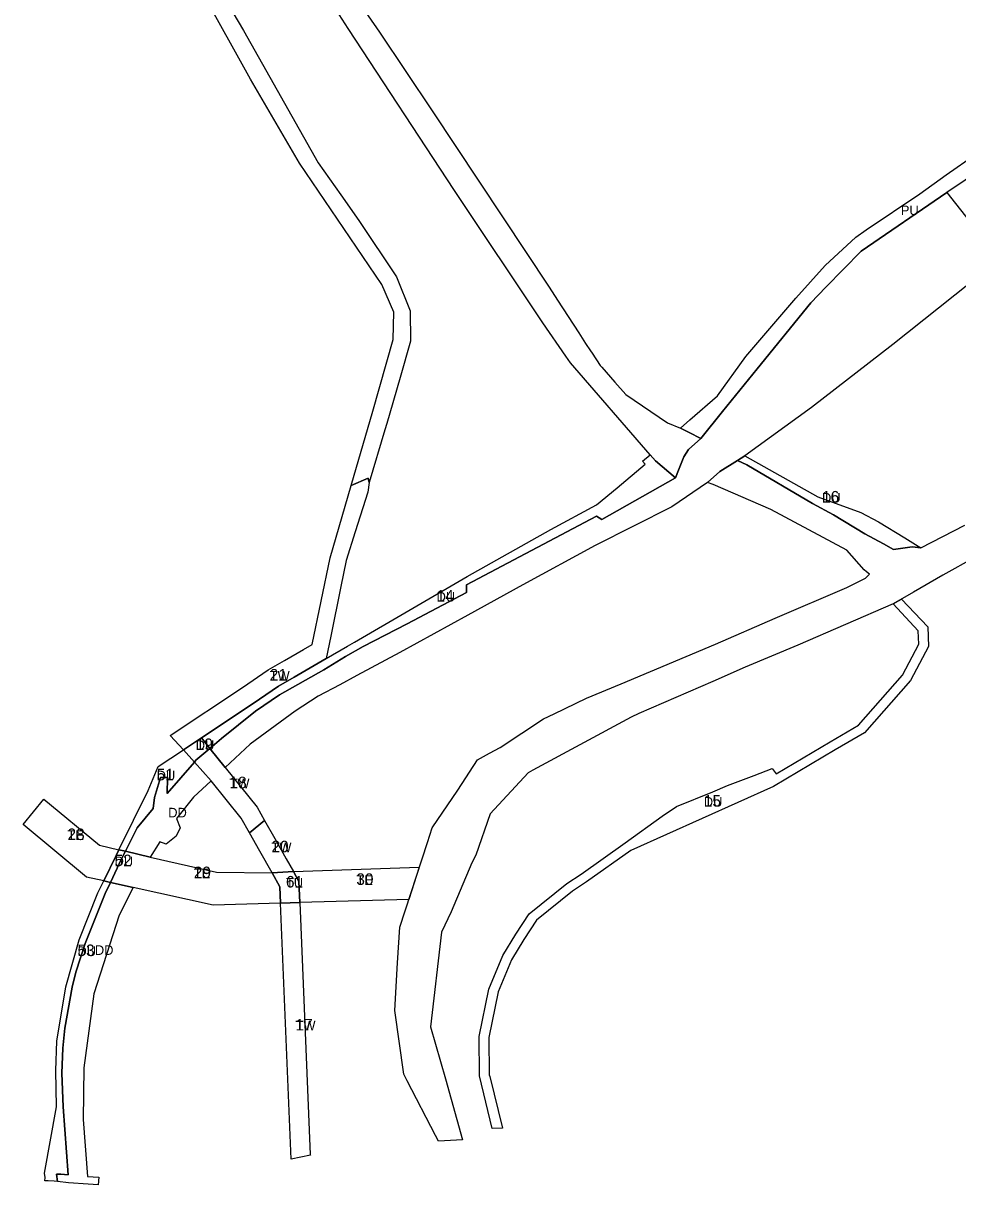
# Model space of a CAD drawing. Extents: x -519992 to -518210, y -1182334 to -1179965.
# Drawn here: x -519396 to -518910, y -1182334 to -1181730 of the extents above; entities that cross this region are included whole.
import ezdxf

# ---------------------------------------------------------------- set-up
doc = ezdxf.new("R2010")
doc.units = 0
for name, color, linetype in [('90310023', 7, 'Continuous'), ('90320013', 7, 'Continuous'), ('90330013', 7, 'Continuous'), ('90380023', 7, 'Continuous'), ('90390023', 7, 'Continuous'), ('90400023', 7, 'Continuous'), ('90450013', 7, 'Continuous'), ('ID_navrh', 7, 'Continuous')]:
    doc.layers.add(name, color=color, linetype=linetype)

msp = doc.modelspace()

# ---------------------------------------------------------------- linework, layer by layer
at = {"layer": '90310023'}
for points in [[(-519262.992, -1182074.289), (-519254.941, -1182069.622), (-519238.255, -1182059.95), (-519227.185, -1182053.534), (-519223.567, -1182051.437), (-519165.02, -1182017.38), (-519121.4, -1181992.9), (-519097.69, -1181980.06), (-519087.01, -1181971.27), (-519072.29, -1181958.97), (-519073.7, -1181957.38), (-519069.77, -1181954.04), (-519067.07, -1181957.19), (-519056.53, -1181966.11), (-519094.94, -1181987.78), (-519097.7, -1181985.93), (-519165.3, -1182021.68), (-519165.22, -1182025.6), (-519196.2, -1182041.94), (-519219.06, -1182053.68), (-519228.29, -1182058.88), (-519239.44, -1182065.85), (-519262.46, -1182078.87), (-519275.09, -1182087.38), (-519292.78, -1182101.58), (-519298.782, -1182106.744), (-519303.172, -1182101.278), (-519276.163, -1182083.414)], [(-518937.284, -1181997.298), (-518928.98, -1182002.39), (-518933.59, -1182001.92), (-518943.302, -1182003.258), (-518948.44, -1182000.47), (-518958.19, -1181995.18), (-518974.49, -1181985.3), (-518985.27, -1181979.47), (-519019.53, -1181959.33), (-519024.41, -1181957.14), (-519020.51, -1181954.59), (-518982.66, -1181976.03), (-518960.26, -1181984.07), (-518951.03, -1181988.87)], [(-519153.446, -1182276.33), (-519153.235, -1182277.183), (-519146.55, -1182304.08), (-519151.97, -1182304.35), (-519158.44, -1182276.94), (-519158.67, -1182256.49), (-519153.61, -1182231.85), (-519146.38, -1182214.41), (-519139.61, -1182203.31), (-519132.61, -1182192.66), (-519113.15, -1182176.92), (-519105.61, -1182172.01), (-519082.7, -1182155.73), (-519063.58, -1182141.86), (-519056.16, -1182136.93), (-519037.12, -1182129.21), (-519029.51, -1182126.07), (-519015.68, -1182120.79), (-519006.27, -1182117.14), (-519004.22, -1182119.96), (-518976.16, -1182103.22), (-518961.45, -1182094.69), (-518938.53, -1182068.6), (-518930.08, -1182052.61), (-518930.34, -1182045.53), (-518943.48, -1182031.64), (-518939.004, -1182029.096), (-518925.412, -1182043.463), (-518925.034, -1182053.763), (-518934.385, -1182071.457), (-518958.234, -1182098.605), (-518973.625, -1182107.53), (-519005.58, -1182126.593), (-519079.784, -1182159.792), (-519102.797, -1182176.144), (-519110.206, -1182180.969), (-519128.86, -1182196.057), (-519135.385, -1182205.986), (-519141.909, -1182216.683), (-519148.808, -1182233.324), (-519153.664, -1182256.97)], [(-519304.082, -1182101.88), (-519303.172, -1182101.278), (-519298.782, -1182106.744), (-519305.96, -1182112.92), (-519306.75, -1182113.832), (-519312.519, -1182107.461)], [(-519325.55, -1182116.08), (-519312.519, -1182107.461), (-519306.75, -1182113.832), (-519320.94, -1182130.21), (-519320.81, -1182121.89), (-519324.42, -1182121.77), (-519327.52, -1182132.32), (-519328.22, -1182137.94), (-519336.51, -1182148.02), (-519342.675, -1182160.214), (-519346.065, -1182159.434), (-519330.82, -1182128.68)], [(-519346.065, -1182159.434), (-519342.675, -1182160.214), (-519344.68, -1182164.18), (-519350.446, -1182176.413), (-519353.952, -1182175.642), (-519347.52, -1182162.37)], [(-519356.97, -1182181.87), (-519353.952, -1182175.642), (-519350.446, -1182176.413), (-519353.15, -1182182.15), (-519363.63, -1182208.08), (-519368.53, -1182223.05), (-519370.36, -1182230.81), (-519374.2, -1182252.07), (-519375.15, -1182262.62), (-519375.73, -1182275.56), (-519374.99, -1182293.06), (-519372.52, -1182328.35), (-519376.2, -1182328.1), (-519378.51, -1182327.95), (-519378.06, -1182331.92), (-519379.66, -1182331.75), (-519382.837, -1182331.574), (-519384.54, -1182331.48), (-519384.34, -1182329.69), (-519384.76, -1182327.55), (-519378.51, -1182293.11), (-519378.89, -1182274.23), (-519378.32, -1182258.87), (-519373.61, -1182230.65), (-519366.78, -1182206.14)]]:
    msp.add_lwpolyline(points, close=True, dxfattribs=at)
at = {"layer": '90320013'}
for points in [[(-519222.31, -1181717.35), (-519210.59, -1181734.41), (-519183.1, -1181775.37), (-519122.3, -1181867), (-519117.928, -1181873.724), (-519106.847, -1181890.769), (-519103.33, -1181896.18), (-519100.73, -1181900.15), (-519099.95, -1181901.33), (-519095.7, -1181907.61), (-519094.93, -1181908.48), (-519088.08, -1181916.29), (-519082.36, -1181922.81), (-519060.67, -1181937.45), (-519054.08, -1181940.22), (-519049.5, -1181942.57), (-519043.36, -1181945.69), (-519049.85, -1181951.39), (-519052.26, -1181955.25), (-519055.06, -1181962.04), (-519056.53, -1181966.11), (-519067.07, -1181957.19), (-519069.77, -1181954.04), (-519111.2, -1181906.26), (-519113.6, -1181902.805), (-519125.64, -1181885.47), (-519171.48, -1181816.66), (-519226.78, -1181732.6), (-519240.87, -1181710.49)], [(-518883.86, -1181997.98), (-518917.64, -1182016.73), (-518932.82, -1182025.58), (-518943.48, -1182031.64), (-518992.91, -1182053.04), (-519020.41, -1182064.46), (-519037.14, -1182071.87), (-519075.61, -1182088.64), (-519079.71, -1182090.45), (-519130.79, -1182118.09), (-519133.19, -1182119.37), (-519152.93, -1182140.79), (-519160.42, -1182162.23), (-519162.51, -1182166.28), (-519173.29, -1182191.64), (-519178.27, -1182202.24), (-519184.01, -1182251.52), (-519176.17, -1182278.4), (-519167.38, -1182310.17), (-519179.83, -1182310.84), (-519181.38, -1182307.96), (-519196.1, -1182279.49), (-519197.91, -1182276), (-519202.63, -1182243.03), (-519201.12, -1182218.25), (-519199.96, -1182199.58), (-519185.65, -1182155.57), (-519183.14, -1182148.05), (-519169.74, -1182128.5), (-519159.6, -1182112.67), (-519153.26, -1182109.16), (-519147.86, -1182106.22), (-519125.18, -1182091.38), (-519119.74, -1182088.73), (-519102.81, -1182080.62), (-519084.93, -1182073.15), (-519035.76, -1182052.6), (-519004.74, -1182039.1), (-518967.5, -1182023), (-518957.82, -1182018.26), (-518955.79, -1182016.24), (-518957.23, -1182014.96), (-518958.48, -1182013.83), (-518967.52, -1182003.69), (-519007.07, -1181982.5), (-519037.03, -1181969.53), (-519040, -1181968.57), (-519033.57, -1181962.86), (-519024.41, -1181957.14), (-519019.53, -1181959.33), (-518985.27, -1181979.47), (-518974.49, -1181985.3), (-518958.19, -1181995.18), (-518948.44, -1182000.47), (-518943.302, -1182003.258), (-518933.59, -1182001.92), (-518928.98, -1182002.39), (-518906.12, -1181990.72)]]:
    msp.add_lwpolyline(points, dxfattribs=at)
at = {"layer": '90330013'}
msp.add_lwpolyline([(-518903.7, -1181865), (-518943.53, -1181896.7), (-518985.81, -1181929.52), (-519020.51, -1181954.59), (-519024.41, -1181957.14), (-519033.57, -1181962.86), (-519040, -1181968.57), (-519058.43, -1181981.09), (-519098.32, -1182001.18), (-519135.97, -1182021.78), (-519164.56, -1182037.39), (-519199.92, -1182056.85), (-519222.3, -1182068.89), (-519231.14, -1182073.63), (-519242.46, -1182079.64), (-519254.35, -1182087.3), (-519277.73, -1182104.52), (-519290.782, -1182116.703), (-519298.782, -1182106.744), (-519292.78, -1182101.58), (-519275.09, -1182087.38), (-519262.46, -1182078.87), (-519239.44, -1182065.85), (-519228.29, -1182058.88), (-519219.06, -1182053.68), (-519196.2, -1182041.94), (-519165.22, -1182025.6), (-519165.3, -1182021.68), (-519097.7, -1181985.93), (-519094.94, -1181987.78), (-519056.53, -1181966.11), (-519055.06, -1181962.04), (-519052.26, -1181955.25), (-519049.85, -1181951.39), (-519043.36, -1181945.69), (-519032.21, -1181931.59), (-519014.2, -1181909.44), (-518986.16, -1181875.1), (-518978.35, -1181867.02), (-518959.96, -1181848.19), (-518915.57, -1181817.81), (-518903.79, -1181832.41)], dxfattribs=at)
for points in [[(-519306.75, -1182113.832), (-519298.113, -1182123.545), (-519307.3, -1182132.12), (-519316.09, -1182143.16), (-519314.14, -1182148.07), (-519316.32, -1182152.28), (-519321.46, -1182156.51), (-519324.83, -1182155.25), (-519329.751, -1182163.186), (-519342.675, -1182160.214), (-519336.51, -1182148.02), (-519328.22, -1182137.94), (-519327.52, -1182132.32), (-519324.42, -1182121.77), (-519320.81, -1182121.89), (-519320.94, -1182130.21)], [(-519350.446, -1182176.413), (-519338.56, -1182179.026), (-519345.85, -1182193.35), (-519359.04, -1182234.21), (-519364.33, -1182272.7), (-519364.66, -1182299.65), (-519362.36, -1182329.2), (-519356.45, -1182329.61), (-519356.83, -1182333.54), (-519362.05, -1182333.21), (-519372.3, -1182332.49), (-519378.06, -1182331.92), (-519378.51, -1182327.95), (-519376.2, -1182328.1), (-519372.52, -1182328.35), (-519374.99, -1182293.06), (-519375.73, -1182275.56), (-519375.15, -1182262.62), (-519374.2, -1182252.07), (-519370.36, -1182230.81), (-519368.53, -1182223.05), (-519363.63, -1182208.08), (-519353.15, -1182182.15)]]:
    msp.add_lwpolyline(points, close=True, dxfattribs=at)
at = {"layer": '90380023'}
msp.add_lwpolyline([(-519252.409, -1182175.819), (-519251.96, -1182186.831), (-519261.956, -1182187.123), (-519262.302, -1182178.644), (-519266.376, -1182171.455), (-519255.258, -1182170.792)], close=True, dxfattribs=at)
at = {"layer": '90390023'}
msp.add_lwpolyline([(-519286.8, -1181724.28), (-519281.3, -1181733.63), (-519242.36, -1181802.29), (-519230.68, -1181818.97), (-519221.32, -1181832.36), (-519201.77, -1181861.67), (-519194.53, -1181879.24), (-519194.44, -1181895.04), (-519199.86, -1181914.01), (-519205.11, -1181932.39), (-519206.76, -1181937.89), (-519207.75, -1181941.19), (-519215.94, -1181968.54), (-519216.49, -1181966.28), (-519225.183, -1181970.09), (-519213.938, -1181931.486), (-519203.481, -1181894.175), (-519203.089, -1181879.993), (-519209.254, -1181865.655), (-519252.151, -1181802.549), (-519277.686, -1181758.823), (-519302.615, -1181713.865)], dxfattribs=at)
for points in [[(-519216.49, -1181966.28), (-519215.94, -1181968.54), (-519216.64, -1181973.55), (-519223.16, -1181994.1), (-519227.85, -1182009.01), (-519230.66, -1182022.59), (-519235.92, -1182048.33), (-519238.255, -1182059.95), (-519254.941, -1182069.622), (-519262.992, -1182074.289), (-519276.163, -1182083.414), (-519304.082, -1182101.88), (-519312.519, -1182107.461), (-519319.308, -1182099.962), (-519281.77, -1182075.133), (-519268.355, -1182065.839), (-519259.955, -1182060.97), (-519250.079, -1182055.246), (-519245.606, -1182052.653), (-519236.113, -1182007.614), (-519225.183, -1181970.09)], [(-519274.231, -1182137.31), (-519270.348, -1182144.162), (-519278.18, -1182150.625), (-519282.533, -1182142.943), (-519298.113, -1182123.545), (-519306.75, -1182113.832), (-519305.96, -1182112.92), (-519298.782, -1182106.744), (-519290.782, -1182116.703)], [(-519258.995, -1182164.197), (-519255.258, -1182170.792), (-519266.376, -1182171.455), (-519272.759, -1182160.191), (-519278.18, -1182150.625), (-519270.348, -1182144.162), (-519265.048, -1182153.515)], [(-519256.526, -1182320.234), (-519261.956, -1182187.123), (-519251.96, -1182186.831), (-519246.615, -1182317.83), (-519246.432, -1182318.162)]]:
    msp.add_lwpolyline(points, close=True, dxfattribs=at)
at = {"layer": '90400023'}
for points in [[(-519356.198, -1182157.104), (-519346.065, -1182159.434), (-519347.52, -1182162.37), (-519353.952, -1182175.642), (-519362.843, -1182173.688), (-519395.814, -1182146.27), (-519385.094, -1182133.074)], [(-519342.675, -1182160.214), (-519329.751, -1182163.186), (-519295.34, -1182171.1), (-519266.376, -1182171.455), (-519262.302, -1182178.644), (-519261.956, -1182187.123), (-519297.063, -1182188.147), (-519338.56, -1182179.026), (-519350.446, -1182176.413), (-519344.68, -1182164.18)], [(-519252.409, -1182175.819), (-519255.258, -1182170.792), (-519189.857, -1182168.509), (-519195.277, -1182185.177), (-519251.96, -1182186.831)]]:
    msp.add_lwpolyline(points, close=True, dxfattribs=at)
at = {"layer": '90450013'}
msp.add_lwpolyline([(-518896.38, -1181804.98), (-518915.57, -1181817.81), (-518959.96, -1181848.19), (-518978.35, -1181867.02), (-518986.16, -1181875.1), (-519014.2, -1181909.44), (-519032.21, -1181931.59), (-519043.36, -1181945.69), (-519049.5, -1181942.57), (-519054.08, -1181940.22), (-519049.15, -1181935.98), (-519034.69, -1181923.51), (-519020.01, -1181903), (-518993.99, -1181872.67), (-518978.77, -1181855.67), (-518962.74, -1181840.92), (-518957.37, -1181837.14), (-518929.6, -1181818.43), (-518915.75, -1181808.56), (-518900.34, -1181797.86)], dxfattribs=at)

# ---------------------------------------------------------------- texts
at = {"layer": '90310023'}
for rotation, p in [(0.0000001, (-518980.398, -1181978.924)), (0, (-519180.8471, -1182030.392)), (360, (-519306.0792, -1182107.555)), (359.9999999, (-519326.4075, -1182123.3321)), (360, (-519041.852, -1182136.9749)), (360, (-519348.3135, -1182167.948)), (360, (-519367.603, -1182214.6557))]:
    msp.add_text('DU', height=5, rotation=rotation, dxfattribs=at).set_placement(p)
at = {"layer": '90330013'}
for rotation, p in [(0.0000001, (-519320.394, -1182142.6063)), (360, (-519358.535, -1182214.0597))]:
    msp.add_text('DD', height=5, rotation=rotation, dxfattribs=at).set_placement(p)
at = {"layer": '90380023'}
msp.add_text('TU', height=5, rotation=0, dxfattribs=at).set_placement((-519259.168, -1182179.0334))
at = {"layer": '90390023'}
for rotation, p in [(0, (-519267.624, -1182071.4567)), (0, (-519288.549, -1182127.468)), (360, (-519266.719, -1182160.7079)), (359.9999999, (-519254.194, -1182253.3258))]:
    msp.add_text('TW', height=5, rotation=rotation, dxfattribs=at).set_placement(p)
at = {"layer": '90400023'}
for rotation, p in [(0, (-519372.794, -1182154.358)), (0, (-519307.1126, -1182174.1805)), (360, (-519222.5847, -1182177.67))]:
    msp.add_text('TE', height=5, rotation=rotation, dxfattribs=at).set_placement(p)
at = {"layer": '90450013'}
msp.add_text('PU', height=5, rotation=0, dxfattribs=at).set_placement((-518939.407, -1181829.545))
at = {"layer": 'ID_navrh'}
for s, rotation, p in [('16', 0, (-518980.398, -1181978.924)), ('14', 360, (-519180.8471, -1182030.392)), ('21', 0, (-519267.624, -1182071.4567)), ('19', 0, (-519306.0792, -1182107.555)), ('51', 360, (-519326.4075, -1182123.3321)), ('18', 0, (-519288.549, -1182127.468)), ('15', 0, (-519041.852, -1182136.9749)), ('28', 360, (-519372.794, -1182154.358)), ('20', 360, (-519266.719, -1182160.7079)), ('52', 0, (-519348.3135, -1182167.948)), ('29', 0, (-519307.1126, -1182174.1805)), ('61', 0, (-519259.168, -1182179.0334)), ('30', 360, (-519222.5847, -1182177.67)), ('53', 0, (-519367.603, -1182214.6557)), ('17', 360, (-519254.194, -1182253.3258))]:
    msp.add_text(s, height=6, rotation=rotation, dxfattribs=at).set_placement(p)

doc.saveas('drawing.dxf')
